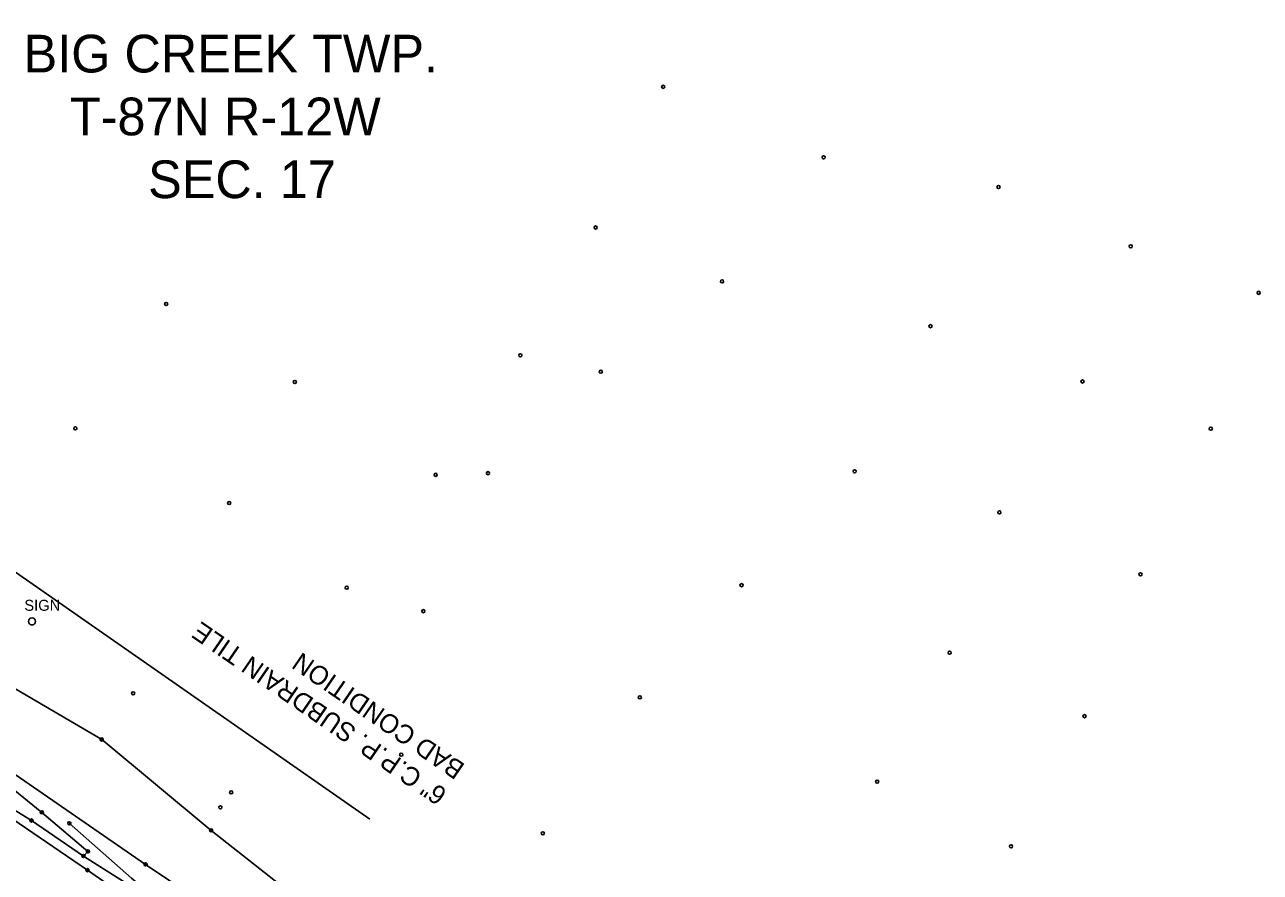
# Model space of a CAD drawing. Extents: x 15502398 to 15534190, y 8766930 to 8782112.
# Drawn here: x 15514814.8 to 15515208.2, y 8779186.3 to 8779456.1 of the extents above; entities that cross this region are included whole.
import ezdxf

# ---------------------------------------------------------------- set-up
doc = ezdxf.new("R2010")
doc.units = 0
for name, color, linetype in [('Default', 7, 'Continuous'), ('EXT_BL', 7, 'Continuous'), ('EXT_D', 7, 'Continuous'), ('EXT_EP', 7, 'Continuous'), ('EXT_SH', 7, 'Continuous'), ('EXT_SNP', 7, 'Continuous'), ('SurControl', 7, 'Continuous'), ('SurPointsNonDTM', 7, 'Continuous'), ('SurRoadPoints', 7, 'Continuous'), ('SurSurveyPoints', 7, 'Continuous'), ('Text', 7, 'Continuous')]:
    doc.layers.add(name, color=color, linetype=linetype)

msp = doc.modelspace()

# ---------------------------------------------------------------- linework, layer by layer
at = {"layer": 'Default'}
msp.add_lwpolyline([(15514893.39, 8779150.63), (15514882.42, 8779158.1), (15514865.06, 8779170.76), (15514848.76, 8779184.39), (15514828.98, 8779201.9)], dxfattribs=at)
at = {"layer": 'EXT_BL'}
msp.add_lwpolyline([(15514797.21, 8779253.2), (15514839.32, 8779228.6), (15514874.17, 8779199.66), (15514911.58, 8779170.08), (15514919.55, 8779154.08), (15514915.79, 8779139.27), (15514906.42, 8779144.7), (15514897.76, 8779150.42), (15514894.68, 8779156.8), (15514892.98, 8779156.33), (15514875.83, 8779173.66), (15514853.31, 8779188.81), (15514802.74, 8779223.63)], dxfattribs=at)
at = {"layer": 'EXT_D'}
msp.add_line((15514561.56, 8779456.11), (15514924.72, 8779203.17), dxfattribs=at)
at = {"layer": 'EXT_EP'}
msp.add_lwpolyline([(15514853.3, 8779174.1), (15514834.8, 8779187), (15514799.88, 8779210.74), (15514777.73, 8779226.07), (15514758.94, 8779238.88), (15514760.07, 8779239.95)], dxfattribs=at)
at = {"layer": 'EXT_SH'}
msp.add_lwpolyline([(15514809.56, 8779207.33), (15514816.96, 8779202.78), (15514833.52, 8779191.48), (15514849.45, 8779181.35), (15514855.47, 8779176.44), (15514862.49, 8779171.48), (15514869.96, 8779166.28), (15514879.58, 8779159.47), (15514886.46, 8779154.67), (15514896.27, 8779148.2)], dxfattribs=at)
at = {"layer": 'EXT_SNP'}
msp.add_lwpolyline([(15514833.52, 8779191.48), (15514834.93, 8779192.95), (15514820.27, 8779205.37), (15514805.27, 8779217.39), (15514781.85, 8779234.07), (15514764.2, 8779246.53), (15514744.94, 8779260.41), (15514730.51, 8779270.81), (15514713.07, 8779282.38), (15514697.61, 8779293.4), (15514681.94, 8779304.22), (15514665.61, 8779315.83), (15514649.42, 8779327.4), (15514633.57, 8779338.27), (15514614.88, 8779351.74), (15514597.04, 8779363.87), (15514577.23, 8779377.53), (15514552.21, 8779395.47)], dxfattribs=at)
at = {"layer": 'SurControl'}
msp.add_circle((15514817.13, 8779266.15), 1.12, dxfattribs=at)
at = {"layer": 'SurPointsNonDTM'}
msp.add_circle((15514828.98, 8779201.9), 0.5, dxfattribs=at)
at = {"layer": 'SurSurveyPoints'}
for centre in [(15515018.09, 8779436.34), (15515069.17, 8779413.9), (15515124.83, 8779404.43), (15514996.58, 8779391.57), (15515166.95, 8779385.57), (15515036.83, 8779374.42), (15515207.7, 8779370.76), (15514859.83, 8779367.23), (15515103.18, 8779360.14), (15514972.6, 8779350.88), (15514998.24, 8779345.64), (15514900.82, 8779342.4), (15515151.59, 8779342.53), (15514830.91, 8779327.62), (15515192.43, 8779327.52), (15515079.05, 8779313.95), (15514945.65, 8779312.84), (15514962.32, 8779313.36), (15514879.91, 8779303.84), (15515125.14, 8779300.89), (15515170.06, 8779281.17), (15514917.33, 8779276.91), (15515043.04, 8779277.72), (15514941.75, 8779269.44), (15515109.27, 8779256.21), (15514849.32, 8779243.29), (15515010.66, 8779242), (15515152.21, 8779236), (15514839.32, 8779228.6), (15514934.68, 8779223.72), (15514880.54, 8779211.74), (15515086.22, 8779215.17), (15514820.27, 8779205.37), (15514877.09, 8779207), (15514816.96, 8779202.78), (15514874.17, 8779199.66), (15514979.76, 8779198.72), (15514834.93, 8779192.95), (15515128.85, 8779194.57), (15514833.52, 8779191.48), (15514833.52, 8779191.48), (15514853.31, 8779188.81), (15514834.8, 8779187)]:
    msp.add_circle(centre, 0.5, dxfattribs=at)

# ---------------------------------------------------------------- texts
at = {"layer": 'SurRoadPoints'}
msp.add_text('SIGN', height=3.498, dxfattribs=at).set_placement((15514814.68, 8779269.55))
at = {"layer": 'Text'}
for s, p in [('BIG CREEK TWP.', (15514814.45, 8779440.91)), ('T-87N R-12W', (15514829.19, 8779420.91)), ('SEC. 17', (15514854.09, 8779400.91))]:
    msp.add_text(s, height=12, dxfattribs=at).set_placement(p)
for s, p in [('6" C.P.P. SUBDRAIN TILE', (15514949.66, 8779212.23)), ('BAD CONDITION', (15514955.33, 8779220.47))]:
    msp.add_text(s, height=6, rotation=145.4923, dxfattribs=at).set_placement(p)

doc.saveas('drawing.dxf')
